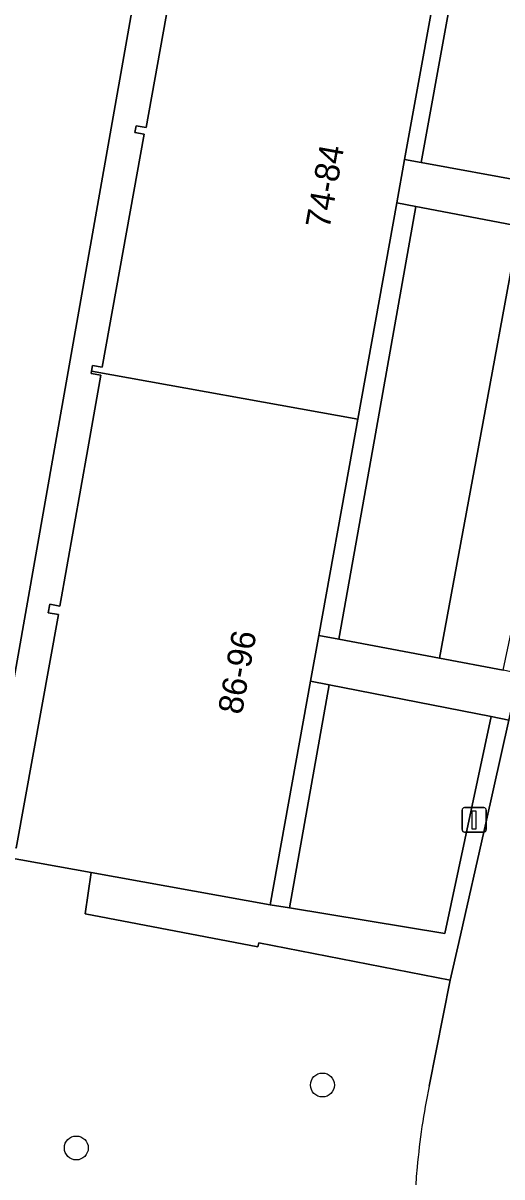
# Model space of a CAD drawing. Extents: x 161402 to 161933, y 381647 to 382315.
# Drawn here: x 161719.49 to 161739.09, y 381720.22 to 381767.41 of the extents above; entities that cross this region are included whole.
import ezdxf

# ---------------------------------------------------------------- set-up
doc = ezdxf.new("R2010")
doc.units = 0
for name, color, linetype in [('IMGEO_Boom', 7, 'Continuous'), ('IMGEO_Groenvoorziening', 7, 'Continuous'), ('IMGEO_Lichtmast', 7, 'Continuous'), ('IMGEO_Pand', 7, 'Continuous'), ('IMGEO_Pand_nummerreeks', 7, 'Continuous'), ('IMGEO_Rijbaan_lokaal_open', 7, 'Continuous'), ('IMGEO_Voetpad_halfverhard', 7, 'Continuous'), ('IMGEO_Voetpad_open', 7, 'Continuous')]:
    doc.layers.add(name, color=color, linetype=linetype)

msp = doc.modelspace()

# ---------------------------------------------------------------- linework, layer by layer
at = {"layer": 'IMGEO_Boom'}
for centre in [(161731.741, 381723.975), (161721.671, 381721.4)]:
    msp.add_circle(centre, 0.489, dxfattribs=at)
at = {"layer": 'IMGEO_Groenvoorziening'}
for points in [[(161752.712, 381793.202), (161751.894, 381793.676), (161728.625, 381808.023), (161725.367, 381800.387), (161728.333, 381792.761), (161720.782, 381750), (161715.379, 381719.409), (161702.956, 381716.799), (161700.216, 381716.223), (161699.316, 381716.034), (161697.703, 381711.335), (161731.537, 381712.814), (161733.72, 381713.227)], [(161719.217, 381733.661), (161720.94, 381743.22), (161720.524, 381743.295), (161720.586, 381743.641), (161720.996, 381743.567), (161722.143, 381750), (161722.68, 381753.011), (161722.28, 381753.082), (161722.297, 381753.177), (161722.338, 381753.407), (161722.724, 381753.337), (161724.443, 381762.871), (161724.064, 381762.939), (161724.114, 381763.215), (161724.523, 381763.142), (161726.26, 381772.781)], [(161736.105, 381723.922), (161736.974, 381728.265), (161729.137, 381729.786), (161729.096, 381729.626), (161722.028, 381730.97), (161722.279, 381732.669), (161718.717, 381733.311)]]:
    msp.add_lwpolyline(points, dxfattribs=at)
for points in [[(161702.956, 381716.799), (161715.379, 381719.409), (161720.782, 381750), (161728.333, 381792.761), (161725.367, 381800.387), (161723.418, 381795.819), (161721.564, 381791.006), (161718.107, 381785.811), (161715.357, 381771.588), (161712.581, 381759.611), (161705.894, 381734.943), (161702.23, 381724.444)], [(161743.366, 381778.862), (161739.042, 381779.66), (161735.779, 381761.706), (161740.106, 381760.913)], [(161732.415, 381742.208), (161736.533, 381741.432), (161738.116, 381750), (161739.797, 381759.102), (161735.559, 381759.906), (161733.8, 381750)], [(161736.533, 381741.432), (161739.131, 381740.943), (161741.06, 381750), (161742.874, 381758.518), (161739.797, 381759.102), (161738.116, 381750)], [(161736.749, 381730.166), (161738.646, 381739.048), (161732.017, 381740.34), (161730.391, 381731.218)]]:
    msp.add_lwpolyline(points, close=True, dxfattribs=at)
for centre, radius, start, end in [((161766.318, 381717.777), 30.832, 168.5045, 174.7269), ((161749.342, 381719.214), 13.796, 174.1902, 198.9774)]:
    msp.add_arc(centre, radius, start, end, dxfattribs=at)
at = {"layer": 'IMGEO_Lichtmast'}
for p, q in [((161737.553, 381735.32), (161738.343, 381735.32)), ((161738.343, 381735.32), (161737.553, 381735.32)), ((161737.453, 381734.42), (161737.453, 381735.22)), ((161737.453, 381735.22), (161737.453, 381734.42)), ((161738.443, 381735.22), (161738.443, 381734.42)), ((161738.443, 381734.42), (161738.443, 381735.22)), ((161738.343, 381734.32), (161737.553, 381734.32)), ((161737.553, 381734.32), (161738.343, 381734.32))]:
    msp.add_line(p, q, dxfattribs=at)
msp.add_lwpolyline([(161737.873, 381735.195), (161738.023, 381735.195), (161738.023, 381734.445), (161737.873, 381734.445), (161737.873, 381735.195)], dxfattribs=at)
for centre, start, end in [((161737.553, 381735.22), 90, 180), ((161737.553, 381735.22), 90, 180), ((161738.343, 381735.22), 0, 90), ((161738.343, 381735.22), 360, 90), ((161737.553, 381734.42), 180, 270), ((161737.553, 381734.42), 180, 270), ((161738.343, 381734.42), 270, 0), ((161738.343, 381734.42), 270, 0)]:
    msp.add_arc(centre, 0.1, start, end, dxfattribs=at)
at = {"layer": 'IMGEO_Pand'}
for points in [[(161736.771, 381771.078), (161725.892, 381773.039), (161725.859, 381772.854), (161726.26, 381772.781), (161724.523, 381763.142), (161724.114, 381763.215), (161724.064, 381762.939), (161724.443, 381762.871), (161722.724, 381753.337), (161722.338, 381753.407), (161722.297, 381753.177), (161733.19, 381751.213), (161734.783, 381760.053), (161735.104, 381761.83)], [(161732.971, 381750), (161733.19, 381751.213), (161722.297, 381753.177), (161722.28, 381753.082), (161722.68, 381753.011), (161722.143, 381750), (161720.996, 381743.567), (161720.586, 381743.641), (161720.524, 381743.295), (161720.94, 381743.22), (161719.217, 381733.661), (161718.794, 381733.737), (161718.717, 381733.311), (161722.279, 381732.669), (161729.607, 381731.348), (161731.255, 381740.488), (161731.594, 381742.363)]]:
    msp.add_lwpolyline(points, close=True, dxfattribs=at)
at = {"layer": 'IMGEO_Rijbaan_lokaal_open'}
msp.add_lwpolyline([(161750.739, 381790.282), (161750.171, 381788.934), (161750.086, 381788.733), (161749.053, 381783.805), (161748.256, 381780.047), (161747.829, 381778.032), (161746.433, 381771.446), (161743.993, 381760.2), (161743.602, 381758.386), (161741.798, 381750), (161740.649, 381744.661), (161739.789, 381740.808), (161739.363, 381738.9), (161738.423, 381734.691), (161737.326, 381729.802), (161736.974, 381728.265), (161736.105, 381723.922)], dxfattribs=at)
for centre, radius, start, end in [((161766.318, 381717.777), 30.832, 168.5045, 174.7269), ((161749.342, 381719.214), 13.796, 174.1902, 198.9774)]:
    msp.add_arc(centre, radius, start, end, dxfattribs=at)
at = {"layer": 'IMGEO_Voetpad_halfverhard'}
for points in [[(161739.042, 381779.66), (161738.341, 381779.789), (161736.771, 381771.078), (161735.104, 381761.83), (161735.779, 381761.706)], [(161735.559, 381759.906), (161734.783, 381760.053), (161733.19, 381751.213), (161732.971, 381750), (161731.594, 381742.363), (161732.415, 381742.208), (161733.8, 381750)], [(161732.017, 381740.34), (161731.255, 381740.488), (161729.607, 381731.348), (161730.391, 381731.218)]]:
    msp.add_lwpolyline(points, close=True, dxfattribs=at)
at = {"layer": 'IMGEO_Voetpad_open'}
for points in [[(161743.993, 381760.2), (161743.283, 381760.33), (161740.106, 381760.913), (161735.779, 381761.706), (161735.104, 381761.83), (161734.783, 381760.053), (161735.559, 381759.906), (161739.797, 381759.102), (161742.874, 381758.518), (161743.602, 381758.386)], [(161739.789, 381740.808), (161739.131, 381740.943), (161736.533, 381741.432), (161732.415, 381742.208), (161731.594, 381742.363), (161731.255, 381740.488), (161732.017, 381740.34), (161738.646, 381739.048), (161739.363, 381738.9)], [(161737.326, 381729.802), (161738.423, 381734.691), (161739.363, 381738.9), (161738.646, 381739.048), (161736.749, 381730.166), (161730.391, 381731.218), (161729.607, 381731.348), (161722.279, 381732.669), (161722.028, 381730.97), (161729.096, 381729.626), (161729.137, 381729.786), (161736.974, 381728.265)]]:
    msp.add_lwpolyline(points, close=True, dxfattribs=at)

# ---------------------------------------------------------------- texts
at = {"layer": 'IMGEO_Pand_nummerreeks'}
for s, rotation, p in [('74-84', 79.7844, (161732.025, 381758.959)), ('86-96', 79.7786, (161728.443, 381739.094))]:
    msp.add_text(s, height=1, rotation=rotation, dxfattribs=at).set_placement(p)

doc.saveas('drawing.dxf')
